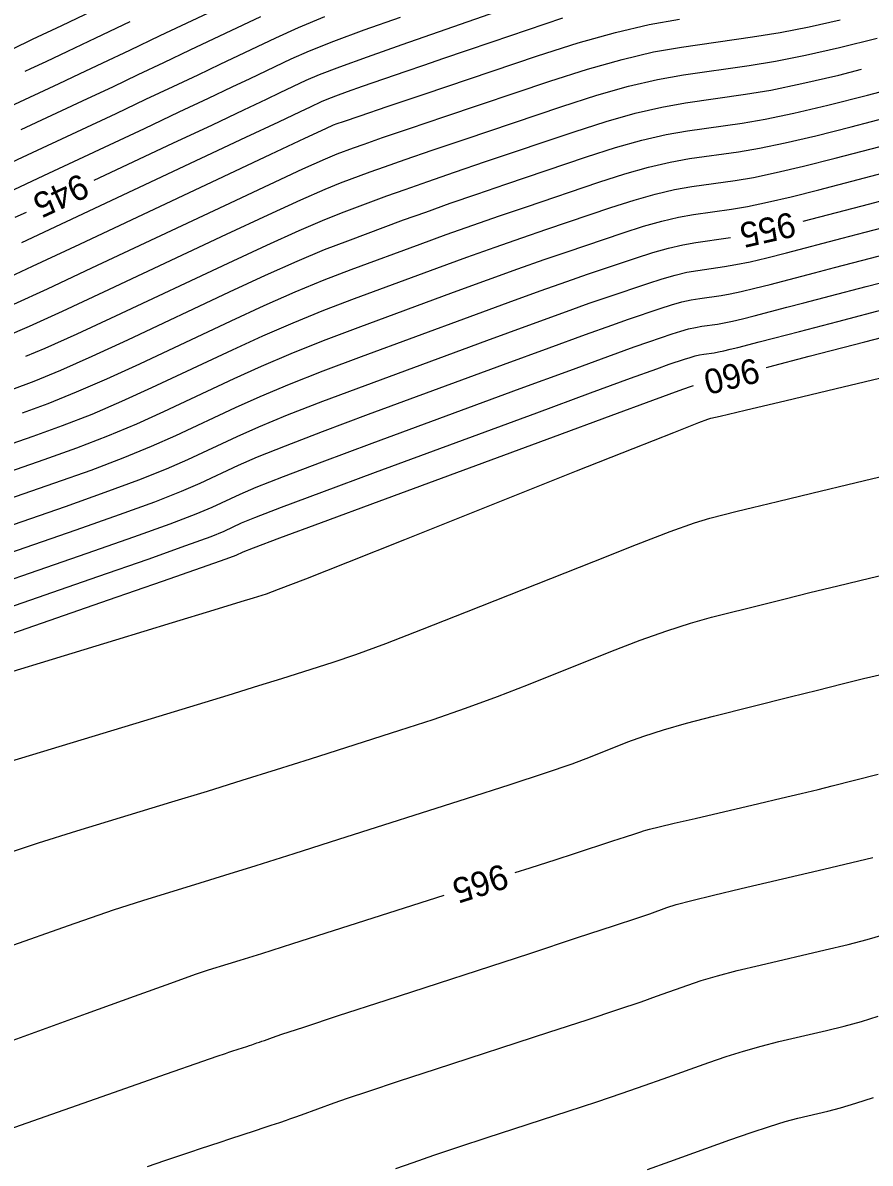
# Model space of a CAD drawing. Extents: x 2175772 to 2185556, y 721391 to 722853.
# Drawn here: x 2178885.4 to 2178980.9, y 721969.8 to 722098.3 of the extents above; entities that cross this region are included whole.
import ezdxf

# ---------------------------------------------------------------- set-up
doc = ezdxf.new("R2010")
doc.units = 0
doc.layers.add('DT_X_Contour_Major', color=7, linetype='Continuous')
doc.layers.add('DT_X_Contour_Minor', color=7, linetype='Continuous')

msp = doc.modelspace()

# ---------------------------------------------------------------- linework, layer by layer
at = {"layer": 'DT_X_Contour_Major'}
for points in [[(2178893.47, 722080.59), (2178902.34, 722084.76), (2178906.82, 722086.86), (2178910.33, 722088.52), (2178912.88, 722089.72), (2178914.45, 722090.47), (2178917.38, 722091.86), (2178918.87, 722092.5), (2178921.17, 722093.39), (2178924.28, 722094.52), (2178928.19, 722095.9), (2178939.69, 722099.9)], [(2178885.72, 722092.88), (2178886.36, 722093.18), (2178888.08, 722093.99), (2178890.52, 722095.15), (2178893.67, 722096.65), (2178897.54, 722098.49)], [(2178885.79, 722060.76), (2178887.96, 722061.68), (2178891.57, 722063.3), (2178895.93, 722065.32), (2178908.56, 722071.26), (2178912.92, 722073.3), (2178916.56, 722074.94), (2178919.47, 722076.19), (2178921.64, 722077.05), (2178926.46, 722078.83), (2178928.52, 722079.57), (2178931.05, 722080.46), (2178934.07, 722081.51), (2178937.57, 722082.7), (2178947.56, 722086.07), (2178951.15, 722087.22), (2178954.44, 722088.15), (2178957.43, 722088.85), (2178960.11, 722089.32), (2178966.85, 722090.28), (2178969.71, 722090.76), (2178973.2, 722091.48), (2178977.35, 722092.45), (2178979.92, 722093.11)], [(2178973.36, 722075.99), (2178980.85, 722077.95), (2178983.77, 722078.72)], [(2178884.59, 722076.42), (2178885.87, 722077.02)], [(2178877.56, 722042.51), (2178889.05, 722046.49), (2178893.14, 722047.94), (2178896.77, 722049.32), (2178899.96, 722050.62), (2178902.7, 722051.84), (2178909.41, 722055), (2178912.18, 722056.24), (2178915.47, 722057.62), (2178919.28, 722059.12), (2178923.61, 722060.75), (2178935.85, 722065.26), (2178940.11, 722066.82), (2178943.74, 722068.14), (2178946.72, 722069.2), (2178949.07, 722070.01), (2178954.46, 722071.83), (2178956.4, 722072.45), (2178958.18, 722072.95), (2178959.79, 722073.33), (2178961.24, 722073.59), (2178964.88, 722074.1), (2178965.17, 722074.15)], [(2178969.16, 722059.51), (2178969.46, 722059.59), (2178974.04, 722060.78), (2178980.28, 722062.4), (2178999.15, 722067.29)], [(2178866.95, 722023.55), (2178870.65, 722024.83), (2178876.75, 722026.95), (2178895.11, 722033.31), (2178901.17, 722035.41), (2178905.58, 722036.96), (2178908.35, 722037.94), (2178909.47, 722038.36), (2178910.26, 722038.73), (2178911.44, 722039.19), (2178914.38, 722040.3), (2178919.1, 722042.05), (2178925.58, 722044.44), (2178945.23, 722051.69), (2178951.71, 722054.08), (2178956.43, 722055.81), (2178959.38, 722056.89), (2178960.56, 722057.32), (2178961.01, 722057.48)], [(2178940.9, 722002.59), (2178942.6, 722003.13), (2178945.53, 722004.07), (2178947.59, 722004.74), (2178951.91, 722006.15), (2178953.34, 722006.61), (2178954.39, 722006.96), (2178955.06, 722007.18), (2178955.35, 722007.28), (2178955.62, 722007.37), (2178956.04, 722007.48), (2178957.11, 722007.74), (2178958.83, 722008.15), (2178961.19, 722008.7), (2178968.35, 722010.38), (2178970.88, 722010.97), (2178973.11, 722011.5), (2178975.02, 722011.97), (2178976.63, 722012.37), (2178981.8, 722013.67)], [(2178838.43, 721967.3), (2178839.81, 721967.79), (2178853.83, 721972.72), (2178859.19, 721974.62), (2178864.75, 721976.6), (2178870.51, 721978.67), (2178876.46, 721980.84), (2178892.61, 721986.72), (2178898.02, 721988.68), (2178902.11, 721990.15), (2178904.9, 721991.14), (2178906.37, 721991.63), (2178908.57, 721992.3), (2178909.93, 721992.72), (2178912.36, 721993.49), (2178915.87, 721994.61), (2178920.45, 721996.06), (2178932.9, 722000.03)]]:
    msp.add_lwpolyline(points, dxfattribs=at)
at = {"layer": 'DT_X_Contour_Minor'}
for points in [[(2178884, 722088.89), (2178889.55, 722091.5), (2178891.83, 722092.57), (2178894.48, 722093.82), (2178897.51, 722095.26), (2178900.93, 722096.89), (2178910.54, 722101.46)], [(2178884.33, 722095.42), (2178886.55, 722096.48), (2178889.83, 722098.04), (2178894.16, 722100.1)], [(2178882.68, 722069.1), (2178886.54, 722070.91), (2178891.87, 722073.41), (2178908.05, 722081.02), (2178913.37, 722083.53), (2178917.21, 722085.33), (2178919.58, 722086.43), (2178920.46, 722086.84), (2178920.84, 722086.98), (2178921.56, 722087.22), (2178923.44, 722087.86), (2178926.48, 722088.89), (2178930.67, 722090.31), (2178943.42, 722094.61), (2178948, 722096.08), (2178952.2, 722097.26), (2178956.01, 722098.16), (2178959.43, 722098.76)], [(2178883.08, 722082.1), (2178886.55, 722083.71), (2178895.95, 722088.13), (2178899.32, 722089.72), (2178902.4, 722091.17), (2178905.19, 722092.49), (2178907.69, 722093.68), (2178913.96, 722096.66), (2178916.51, 722097.81), (2178919.48, 722099.03)], [(2178883.83, 722079.26), (2178887.83, 722081.12), (2178899.14, 722086.44), (2178903.07, 722088.29), (2178906.37, 722089.84), (2178909.03, 722091.11), (2178911.07, 722092.07), (2178915.67, 722094.26), (2178917.73, 722095.17), (2178920.47, 722096.26), (2178923.89, 722097.53), (2178928, 722098.99)], [(2178884.44, 722066.63), (2178888.22, 722068.37), (2178893.22, 722070.72), (2178908.22, 722077.77), (2178913.22, 722080.12), (2178917, 722081.87), (2178919.54, 722083.02), (2178920.85, 722083.58), (2178922.71, 722084.26), (2178923.88, 722084.67), (2178925.97, 722085.4), (2178929.01, 722086.43), (2178932.97, 722087.77), (2178944.8, 722091.77), (2178949.05, 722093.13), (2178952.94, 722094.22), (2178956.48, 722095.05), (2178959.65, 722095.61), (2178967.64, 722096.74), (2178970.74, 722097.24), (2178974.03, 722097.88), (2178977.53, 722098.66)], [(2178885.28, 722086.3), (2178892.75, 722089.81), (2178895.57, 722091.14), (2178898.44, 722092.5), (2178901.35, 722093.88), (2178904.31, 722095.28), (2178912.25, 722099.06)], [(2178885.34, 722073.58), (2178890.38, 722075.95), (2178905.54, 722083.07), (2178910.57, 722085.44), (2178914.29, 722087.19), (2178916.72, 722088.33), (2178917.84, 722088.86), (2178919.08, 722089.46), (2178919.72, 722089.73), (2178920.71, 722090.11), (2178922.03, 722090.59), (2178923.7, 722091.18), (2178928.62, 722092.89), (2178930.6, 722093.58), (2178932.88, 722094.36), (2178935.44, 722095.23), (2178938.3, 722096.2), (2178946.29, 722098.9)], [(2178883.5, 722062.98), (2178886.2, 722064.15), (2178889.9, 722065.84), (2178894.58, 722068.02), (2178908.39, 722074.52), (2178913.07, 722076.71), (2178916.78, 722078.4), (2178919.5, 722079.61), (2178921.25, 722080.31), (2178924.59, 722081.55), (2178926.2, 722082.12), (2178928.51, 722082.93), (2178931.54, 722083.97), (2178935.27, 722085.23), (2178946.18, 722088.92), (2178950.1, 722090.18), (2178953.69, 722091.19), (2178956.95, 722091.95), (2178959.88, 722092.46), (2178967.25, 722093.51), (2178970.22, 722094), (2178973.62, 722094.68), (2178977.44, 722095.56), (2178981.68, 722096.62)], [(2178884.21, 722057.03), (2178886.71, 722057.96), (2178889.73, 722059.21), (2178893.25, 722060.76), (2178897.29, 722062.63), (2178908.73, 722068.01), (2178912.78, 722069.89), (2178916.34, 722071.47), (2178919.43, 722072.78), (2178922.04, 722073.79), (2178928.34, 722076.12), (2178930.83, 722077.02), (2178933.59, 722078), (2178936.6, 722079.04), (2178939.87, 722080.16), (2178948.94, 722083.22), (2178952.2, 722084.27), (2178955.19, 722085.11), (2178957.9, 722085.74), (2178960.33, 722086.17), (2178966.46, 722087.04), (2178969.07, 722087.48), (2178972.29, 722088.15), (2178976.13, 722089.06), (2178980.59, 722090.19), (2178993.3, 722093.51)], [(2178885.42, 722054.39), (2178888.32, 722055.46), (2178891.49, 722056.74), (2178894.93, 722058.23), (2178898.64, 722059.93), (2178908.9, 722064.76), (2178912.63, 722066.48), (2178916.13, 722068.01), (2178919.39, 722069.36), (2178922.43, 722070.53), (2178930.22, 722073.4), (2178933.15, 722074.47), (2178936.13, 722075.53), (2178939.13, 722076.58), (2178942.17, 722077.62), (2178950.32, 722080.37), (2178953.25, 722081.31), (2178955.94, 722082.07), (2178958.37, 722082.64), (2178960.56, 722083.03), (2178966.07, 722083.81), (2178968.41, 722084.2), (2178971.3, 722084.81), (2178974.76, 722085.62), (2178978.76, 722086.63), (2178990.19, 722089.62)], [(2178877.88, 722048.73), (2178886.63, 722051.76), (2178889.92, 722052.95), (2178893.25, 722054.26), (2178896.61, 722055.69), (2178899.99, 722057.23), (2178909.07, 722061.5), (2178912.48, 722063.07), (2178915.91, 722064.55), (2178919.36, 722065.95), (2178922.82, 722067.27), (2178932.09, 722070.69), (2178935.47, 722071.92), (2178938.66, 722073.07), (2178941.66, 722074.12), (2178944.47, 722075.08), (2178951.7, 722077.53), (2178954.3, 722078.36), (2178956.68, 722079.03), (2178958.84, 722079.54), (2178960.79, 722079.88), (2178965.67, 722080.57), (2178967.75, 722080.92), (2178970.32, 722081.46), (2178973.38, 722082.18), (2178976.94, 722083.08), (2178987.08, 722085.73)], [(2178877.72, 722045.62), (2178887.84, 722049.12), (2178891.53, 722050.45), (2178895.01, 722051.79), (2178898.28, 722053.15), (2178901.35, 722054.54), (2178909.24, 722058.25), (2178912.33, 722059.65), (2178915.69, 722061.08), (2178919.32, 722062.53), (2178923.22, 722064.01), (2178933.97, 722067.97), (2178937.79, 722069.37), (2178941.2, 722070.6), (2178944.19, 722071.66), (2178946.77, 722072.55), (2178953.08, 722074.68), (2178955.35, 722075.41), (2178957.43, 722075.99), (2178959.32, 722076.43), (2178961.01, 722076.73), (2178965.28, 722077.34), (2178967.09, 722077.65), (2178969.34, 722078.11), (2178972.01, 722078.74), (2178975.11, 722079.53), (2178983.97, 722081.84)], [(2178877.4, 722039.39), (2178890.26, 722043.85), (2178894.74, 722045.44), (2178898.53, 722046.85), (2178901.64, 722048.08), (2178904.05, 722049.14), (2178909.58, 722051.74), (2178912.03, 722052.83), (2178915.26, 722054.15), (2178919.25, 722055.7), (2178924.01, 722057.49), (2178937.72, 722062.54), (2178942.43, 722064.28), (2178946.28, 722065.67), (2178949.25, 722066.74), (2178951.37, 722067.47), (2178955.84, 722068.98), (2178957.45, 722069.5), (2178958.93, 722069.92), (2178960.26, 722070.23), (2178961.47, 722070.44), (2178964.49, 722070.87), (2178965.78, 722071.09), (2178967.37, 722071.42), (2178969.26, 722071.86), (2178971.46, 722072.42), (2178977.74, 722074.06), (2178980.33, 722074.74), (2178983.37, 722075.53)], [(2178877.23, 722036.28), (2178891.47, 722041.22), (2178896.35, 722042.93), (2178900.3, 722044.37), (2178903.32, 722045.55), (2178905.41, 722046.45), (2178909.75, 722048.49), (2178911.88, 722049.42), (2178915.04, 722050.69), (2178919.21, 722052.29), (2178924.4, 722054.23), (2178939.6, 722059.83), (2178944.75, 722061.73), (2178948.81, 722063.21), (2178951.79, 722064.28), (2178953.67, 722064.94), (2178957.22, 722066.14), (2178958.5, 722066.55), (2178959.67, 722066.88), (2178960.74, 722067.13), (2178961.69, 722067.29), (2178964.1, 722067.63), (2178965.12, 722067.81), (2178966.38, 722068.07), (2178967.89, 722068.42), (2178969.64, 722068.87), (2178974.63, 722070.17), (2178976.88, 722070.76), (2178979.9, 722071.55), (2178983.68, 722072.53)], [(2178877.07, 722033.17), (2178892.68, 722038.58), (2178897.96, 722040.43), (2178902.06, 722041.9), (2178904.99, 722043.01), (2178906.76, 722043.75), (2178909.92, 722045.24), (2178911.73, 722046.01), (2178914.82, 722047.23), (2178919.17, 722048.88), (2178924.79, 722050.96), (2178941.48, 722057.12), (2178947.07, 722059.18), (2178951.35, 722060.74), (2178954.32, 722061.82), (2178955.96, 722062.4), (2178958.6, 722063.29), (2178959.55, 722063.59), (2178960.42, 722063.84), (2178961.21, 722064.02), (2178961.92, 722064.15), (2178963.7, 722064.4), (2178964.46, 722064.53), (2178965.4, 722064.72), (2178966.52, 722064.99), (2178967.81, 722065.32), (2178971.51, 722066.28), (2178973.43, 722066.78), (2178976.42, 722067.56), (2178980.46, 722068.61), (2178985.57, 722069.94)], [(2178876.91, 722030.06), (2178893.9, 722035.94), (2178899.56, 722037.92), (2178903.82, 722039.43), (2178906.67, 722040.47), (2178908.11, 722041.06), (2178910.09, 722041.98), (2178911.59, 722042.6), (2178914.6, 722043.76), (2178919.14, 722045.46), (2178925.19, 722047.7), (2178943.35, 722054.4), (2178949.39, 722056.63), (2178953.89, 722058.28), (2178956.85, 722059.36), (2178958.26, 722059.86), (2178959.98, 722060.44), (2178960.6, 722060.64), (2178961.17, 722060.8), (2178961.68, 722060.92), (2178962.15, 722061), (2178963.31, 722061.17), (2178963.8, 722061.25), (2178964.41, 722061.38), (2178965.14, 722061.55), (2178965.99, 722061.76), (2178968.4, 722062.39), (2178969.99, 722062.81), (2178972.94, 722063.57), (2178977.25, 722064.69), (2178982.93, 722066.17)], [(2178876.7, 722022.96), (2178895.93, 722028.81), (2178902.31, 722030.75), (2178907.02, 722032.19), (2178910.06, 722033.12), (2178911.44, 722033.54), (2178912.88, 722034), (2178914.25, 722034.51), (2178917.31, 722035.7), (2178922.05, 722037.58), (2178928.47, 722040.13), (2178947.82, 722047.84), (2178954.19, 722050.37), (2178958.77, 722052.19), (2178961.58, 722053.3), (2178962.6, 722053.69), (2178962.95, 722053.78), (2178963.98, 722054.03), (2178966.81, 722054.7), (2178971.43, 722055.8), (2178977.85, 722057.34), (2178997.37, 722061.99)], [(2178884.11, 722015.13), (2178899.09, 722019.68), (2178904.27, 722021.26), (2178908.59, 722022.59), (2178912.05, 722023.66), (2178914.64, 722024.47), (2178920.4, 722026.31), (2178922.96, 722027.18), (2178926.32, 722028.41), (2178930.48, 722030), (2178935.44, 722031.96), (2178949.75, 722037.66), (2178954.59, 722039.57), (2178958.38, 722041.02), (2178961.12, 722042), (2178962.82, 722042.53), (2178965.93, 722043.32), (2178967.64, 722043.74), (2178970.45, 722044.42), (2178974.34, 722045.35), (2178979.33, 722046.54), (2178994.07, 722050.06)], [(2178882.34, 722004.31), (2178887.23, 722005.94), (2178891.53, 722007.29), (2178902.25, 722010.55), (2178906.24, 722011.77), (2178910.17, 722012.99), (2178914.03, 722014.2), (2178917.84, 722015.41), (2178927.92, 722018.62), (2178931.66, 722019.85), (2178935.32, 722021.12), (2178938.91, 722022.43), (2178942.42, 722023.8), (2178951.68, 722027.49), (2178955, 722028.77), (2178957.99, 722029.84), (2178960.67, 722030.71), (2178963.03, 722031.37), (2178968.91, 722032.85), (2178971.3, 722033.45), (2178974.08, 722034.13), (2178977.25, 722034.9), (2178980.8, 722035.75), (2178990.77, 722038.13)], [(2178883.81, 721994.22), (2178890.61, 721996.64), (2178895.66, 721998.39), (2178898.95, 721999.46), (2178905.41, 722001.43), (2178908.2, 722002.29), (2178911.74, 722003.39), (2178916.02, 722004.74), (2178921.04, 722006.34), (2178935.44, 722010.93), (2178940.36, 722012.51), (2178944.32, 722013.82), (2178947.34, 722014.86), (2178949.4, 722015.63), (2178953.61, 722017.31), (2178955.4, 722017.96), (2178957.6, 722018.67), (2178960.22, 722019.41), (2178963.25, 722020.21), (2178971.89, 722022.39), (2178974.97, 722023.16), (2178977.72, 722023.85), (2178980.16, 722024.44), (2178982.27, 722024.95)], [(2178858.4, 721964.69), (2178885.95, 721974.39), (2178895.04, 721977.59), (2178901.63, 721979.91), (2178905.73, 721981.34), (2178907.33, 721981.9), (2178908.29, 721982.22), (2178908.65, 721982.34), (2178909.01, 721982.46), (2178909.72, 721982.69), (2178910.67, 721983.01), (2178910.99, 721983.11), (2178911.24, 721983.2), (2178911.44, 721983.26), (2178911.81, 721983.39), (2178911.94, 721983.43), (2178912.12, 721983.49), (2178912.37, 721983.58), (2178912.67, 721983.69), (2178913.57, 721984.02), (2178914.62, 721984.37), (2178917.1, 721985.19), (2178921.02, 721986.47), (2178926.37, 721988.22), (2178942.54, 721993.49), (2178947.93, 721995.26), (2178951.99, 721996.59), (2178954.71, 721997.49), (2178956.09, 721997.96), (2178957.98, 721998.65), (2178959.04, 721998.98), (2178960.8, 721999.44), (2178963.24, 722000.05), (2178966.38, 722000.8), (2178975.69, 722002.97), (2178978.81, 722003.71), (2178981.21, 722004.3)], [(2178899.48, 721969.49), (2178901.44, 721970.16), (2178904.37, 721971.13), (2178905.47, 721971.5), (2178907.66, 721972.22), (2178908.75, 721972.58), (2178911.64, 721973.54), (2178912.63, 721973.86), (2178913.41, 721974.12), (2178914.39, 721974.45), (2178915.15, 721974.7), (2178915.53, 721974.83), (2178916.1, 721975.03), (2178916.85, 721975.3), (2178920.52, 721976.64), (2178922.01, 721977.16), (2178924.43, 721977.97), (2178927.78, 721979.08), (2178932.06, 721980.48), (2178944.71, 721984.6), (2178949.02, 721986.01), (2178952.48, 721987.16), (2178955.08, 721988.04), (2178956.83, 721988.65), (2178960.35, 721989.92), (2178961.85, 721990.42), (2178963.71, 721990.96), (2178965.93, 721991.54), (2178968.5, 721992.17), (2178975.84, 721993.88), (2178978.4, 721994.5), (2178980.57, 721995.06), (2178982.34, 721995.57)], [(2178927.48, 721969.25), (2178929.41, 721969.94), (2178931.76, 721970.75), (2178934.55, 721971.68), (2178937.75, 721972.73), (2178946.87, 721975.71), (2178950.1, 721976.77), (2178952.97, 721977.73), (2178955.45, 721978.59), (2178957.57, 721979.34), (2178962.72, 721981.2), (2178964.66, 721981.87), (2178966.63, 721982.48), (2178968.61, 721983.04), (2178970.62, 721983.54), (2178975.99, 721984.8), (2178977.98, 721985.29), (2178979.92, 721985.83), (2178981.81, 721986.41)], [(2178955.83, 721969.13), (2178958.31, 721970.02), (2178965.09, 721972.48), (2178967.48, 721973.32), (2178969.54, 721974), (2178971.3, 721974.54), (2178972.73, 721974.91), (2178976.14, 721975.71), (2178977.56, 721976.08), (2178979.28, 721976.6), (2178981.28, 721977.25)]]:
    msp.add_lwpolyline(points, dxfattribs=at)

# ---------------------------------------------------------------- texts
at = {"layer": 'DT_X_Contour_Major'}
for s, rotation, p in [('945', 205.1403, (2178891.99, 722081.44)), ('955', 192.6701, (2178972.11, 722077.05)), ('960', 194.0221, (2178968, 722060.62)), ('965', 197.7067, (2178939.55, 722003.63))]:
    msp.add_text(s, height=2.8, rotation=rotation, dxfattribs=at).set_placement(p)

doc.saveas('drawing.dxf')
